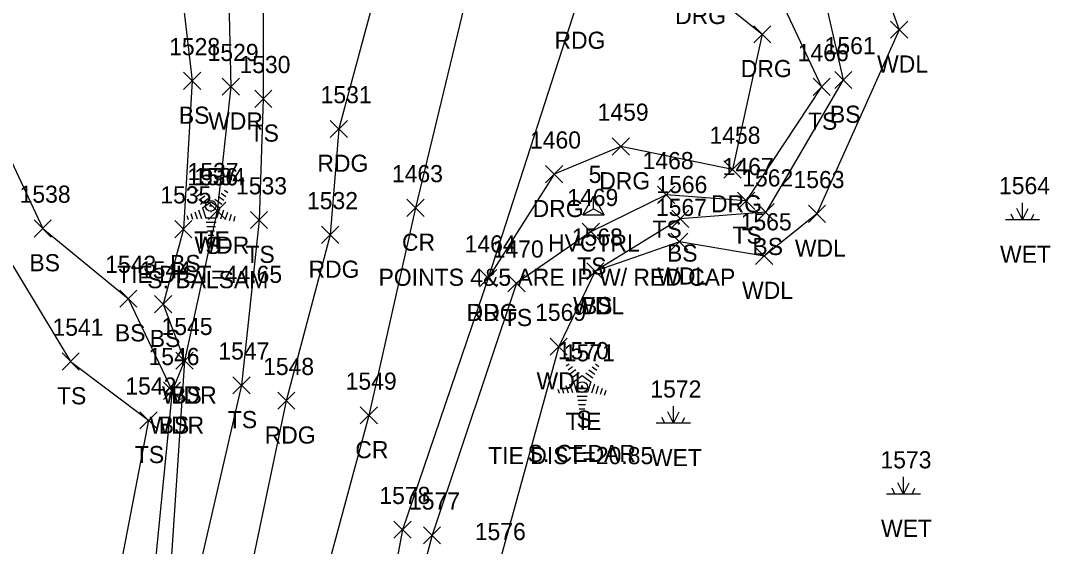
# Model space of a CAD drawing. Extents: x 1678553 to 1680768, y 787260 to 792325.
# Drawn here: x 1678621 to 1678741.1, y 787363.9 to 787425.2 of the extents above; entities that cross this region are included whole.
import ezdxf

# ---------------------------------------------------------------- set-up
doc = ezdxf.new("R2010")
doc.units = 0
for name, color, linetype in [('C_A', 7, 'Continuous'), ('C_C', 7, 'Continuous'), ('C_I', 7, 'Continuous'), ('CBP', 7, 'Continuous'), ('CPSM', 7, 'Continuous'), ('L_A', 7, 'Continuous'), ('L_C', 7, 'Continuous'), ('L_I', 7, 'Continuous'), ('L_TIC', 7, 'Continuous'), ('LAWA', 7, 'Continuous'), ('LELB', 7, 'Continuous'), ('LTC', 7, 'Continuous'), ('LWET', 7, 'Continuous'), ('P_A', 7, 'Continuous'), ('P_I', 7, 'Continuous'), ('P_TIC', 7, 'Continuous'), ('PEU', 7, 'Continuous'), ('PRC', 7, 'Continuous'), ('R_A', 7, 'Continuous'), ('R_I', 7, 'Continuous'), ('R_TIC', 7, 'Continuous'), ('RDG', 7, 'Continuous')]:
    doc.layers.add(name, color=color, linetype=linetype)

msp = doc.modelspace()

# ---------------------------------------------------------------- linework, layer by layer
at = {"layer": 'CBP'}
for centre, radius in [((1678643.19, 787403.64), 0.625), ((1678643.19, 787403.64), 0.0833), ((1678686.51, 787382.49), 0.625), ((1678686.51, 787382.49), 0.0833)]:
    msp.add_circle(centre, radius, dxfattribs=at)
at = {"layer": 'CPSM'}
for p, q in [((1678686.59, 787402.58), (1678687.84, 787404.75)), ((1678689.09, 787402.58), (1678687.84, 787404.75)), ((1678687.84, 787403.3), (1678687.84, 787404.75)), ((1678686.59, 787402.58), (1678687.84, 787403.3)), ((1678687.84, 787403.3), (1678687.84, 787403.3)), ((1678687.84, 787403.3), (1678689.09, 787402.58)), ((1678686.59, 787402.58), (1678689.09, 787402.58))]:
    msp.add_line(p, q, dxfattribs=at)
at = {"layer": 'L_TIC'}
for points in [[(1678722.5, 787423.18), (1678724.5, 787425.18)], [(1678724.5, 787423.18), (1678722.5, 787425.18)], [(1678640.03, 787417.21), (1678642.03, 787419.21)], [(1678642.03, 787417.21), (1678640.03, 787419.21)], [(1678644.53, 787416.53), (1678646.53, 787418.53)], [(1678646.53, 787416.53), (1678644.53, 787418.53)], [(1678713.45, 787416.51), (1678715.45, 787418.51)], [(1678715.45, 787416.51), (1678713.45, 787418.51)], [(1678715.98, 787417.32), (1678717.98, 787419.32)], [(1678717.98, 787417.32), (1678715.98, 787419.32)], [(1678648.32, 787415.12), (1678650.32, 787417.12)], [(1678650.32, 787415.12), (1678648.32, 787417.12)], [(1678695.31, 787403.91), (1678697.31, 787405.91)], [(1678697.31, 787403.91), (1678695.31, 787405.91)], [(1678704.65, 787403.22), (1678706.65, 787405.22)], [(1678706.65, 787403.22), (1678704.65, 787405.22)], [(1678642.94, 787402.04), (1678644.94, 787404.04)], [(1678644.94, 787402.04), (1678642.94, 787404.04)], [(1678647.83, 787400.97), (1678649.83, 787402.97)], [(1678649.83, 787400.97), (1678647.83, 787402.97)], [(1678696.96, 787401.12), (1678698.96, 787403.12)], [(1678698.96, 787401.12), (1678696.96, 787403.12)], [(1678706.93, 787401.89), (1678708.93, 787403.89)], [(1678708.93, 787401.89), (1678706.93, 787403.89)], [(1678712.91, 787401.7), (1678714.91, 787403.7)], [(1678714.91, 787401.7), (1678712.91, 787403.7)], [(1678622.59, 787399.99), (1678624.59, 787401.99)], [(1678624.59, 787399.99), (1678622.59, 787401.99)], [(1678639, 787399.91), (1678641, 787401.91)], [(1678641, 787399.91), (1678639, 787401.91)], [(1678686.53, 787399.61), (1678688.53, 787401.61)], [(1678688.53, 787399.61), (1678686.53, 787401.61)], [(1678696.86, 787398.45), (1678698.86, 787400.45)], [(1678698.86, 787398.45), (1678696.86, 787400.45)], [(1678706.75, 787396.77), (1678708.75, 787398.77)], [(1678708.75, 787396.77), (1678706.75, 787398.77)], [(1678687.05, 787394.99), (1678689.05, 787396.99)], [(1678689.05, 787394.99), (1678687.05, 787396.99)], [(1678687.05, 787394.99), (1678689.05, 787396.99)], [(1678689.05, 787394.99), (1678687.05, 787396.99)], [(1678677.86, 787393.6), (1678679.86, 787395.6)], [(1678679.86, 787393.6), (1678677.86, 787395.6)], [(1678632.57, 787391.81), (1678634.57, 787393.81)], [(1678634.57, 787391.81), (1678632.57, 787393.81)], [(1678636.64, 787391.16), (1678638.64, 787393.16)], [(1678638.64, 787391.16), (1678636.64, 787393.16)], [(1678682.78, 787386.21), (1678684.78, 787388.21)], [(1678684.78, 787386.21), (1678682.78, 787388.21)], [(1678625.85, 787384.47), (1678627.85, 787386.47)], [(1678627.85, 787384.47), (1678625.85, 787386.47)], [(1678639.14, 787384.56), (1678641.14, 787386.56)], [(1678641.14, 787384.56), (1678639.14, 787386.56)], [(1678639.14, 787384.56), (1678641.14, 787386.56)], [(1678641.14, 787384.56), (1678639.14, 787386.56)], [(1678645.78, 787381.69), (1678647.78, 787383.69)], [(1678647.78, 787381.69), (1678645.78, 787383.69)], [(1678637.68, 787381.05), (1678639.68, 787383.05)], [(1678639.68, 787381.05), (1678637.68, 787383.05)], [(1678637.68, 787381.05), (1678639.68, 787383.05)], [(1678639.68, 787381.05), (1678637.68, 787383.05)], [(1678634.93, 787377.61), (1678636.93, 787379.61)], [(1678636.93, 787377.61), (1678634.93, 787379.61)], [(1678668.01, 787364.19), (1678670.01, 787366.19)], [(1678670.01, 787364.19), (1678668.01, 787366.19)]]:
    msp.add_lwpolyline(points, dxfattribs=at)
at = {"layer": 'LAWA'}
for points in [[(1678709.78, 787516.49), (1678712.28, 787497.22), (1678701.79, 787461.31), (1678703.15, 787457.42), (1678705.06, 787457.53), (1678706.33, 787458.18), (1678713.92, 787445.73), (1678717.92, 787439.61), (1678723.5, 787424.18), (1678713.91, 787402.7), (1678707.75, 787397.77), (1678697.86, 787399.45), (1678688.05, 787395.99), (1678683.78, 787387.21), (1678676.74, 787361.63), (1678672.53, 787349.76), (1678668.76, 787338.44), (1678662.12, 787319.95), (1678654.2, 787273.36)], [(1678664.87, 787478.76), (1678656.17, 787475.05), (1678649.55, 787452.64), (1678645.06, 787437.85), (1678645.53, 787417.53), (1678643.94, 787403.04), (1678640.14, 787385.56), (1678638.68, 787382.05), (1678636.34, 787358.01), (1678630, 787335.83), (1678617.26, 787305.35), (1678619.26, 787283.6)]]:
    msp.add_lwpolyline(points, dxfattribs=at)
at = {"layer": 'LELB'}
for points in [[(1678703.25, 787521.16), (1678708.08, 787504.89), (1678710.05, 787496.73), (1678699.74, 787468.92), (1678698.82, 787457.49), (1678706.75, 787433.93), (1678714.45, 787417.51), (1678705.65, 787404.22), (1678696.31, 787404.91), (1678687.53, 787400.61), (1678678.86, 787394.6), (1678669.01, 787365.19), (1678664.74, 787349.08), (1678657.46, 787321.28), (1678652.34, 787297.83), (1678647.47, 787276.32)], [(1678680.77, 787518.06), (1678676.3, 787498.71), (1678671.38, 787486.28), (1678667.84, 787478.11), (1678658.92, 787472.2), (1678652.16, 787452.17), (1678649.27, 787436.42), (1678649.32, 787416.12), (1678648.83, 787401.97), (1678646.78, 787382.69), (1678641.04, 787357.73), (1678634.18, 787333.53), (1678626.23, 787302.07), (1678622.91, 787282.59)], [(1678670.34, 787510.61), (1678668.53, 787502.63), (1678666.36, 787491.77), (1678660.38, 787481.94), (1678643.3, 787471.26), (1678637.93, 787460.78), (1678638.18, 787442.6), (1678641.03, 787418.21), (1678640, 787400.91), (1678637.64, 787392.16), (1678640.14, 787385.56), (1678638.3, 787358.26), (1678630, 787335.83)], [(1678714.02, 787439.74), (1678712.73, 787436.98), (1678716.98, 787418.32), (1678707.93, 787402.89), (1678697.96, 787402.12), (1678688.05, 787395.99)], [(1678615.65, 787417.95), (1678623.59, 787400.99), (1678633.57, 787392.81), (1678638.68, 787382.05)], [(1678606.34, 787416.23), (1678617.44, 787401.01), (1678626.85, 787385.47), (1678635.93, 787378.61), (1678632.1, 787358.6), (1678630, 787335.83)]]:
    msp.add_lwpolyline(points, dxfattribs=at)
at = {"layer": 'LTC'}
for p, q in [((1678641.38, 787405.23), (1678641.74, 787405.49)), ((1678644.78, 787405.47), (1678645.2, 787405.17)), ((1678641.59, 787404.76), (1678642.12, 787405.15)), ((1678641.8, 787404.3), (1678642.51, 787404.81)), ((1678642.01, 787403.83), (1678642.89, 787404.47)), ((1678642.24, 787403.38), (1678643.25, 787404.11)), ((1678643.25, 787404.11), (1678644.25, 787403.39)), ((1678643.67, 787404.42), (1678644.48, 787403.84)), ((1678644.04, 787404.77), (1678644.72, 787404.28)), ((1678644.41, 787405.12), (1678644.96, 787404.72)), ((1678641.33, 787402.94), (1678641.6, 787402.11)), ((1678641.78, 787403.16), (1678642.11, 787402.14)), ((1678642.24, 787403.38), (1678642.62, 787402.18)), ((1678644.25, 787403.39), (1678643.85, 787402.18)), ((1678644.68, 787403.12), (1678644.35, 787402.08)), ((1678645.13, 787402.87), (1678644.84, 787401.98)), ((1678640.42, 787402.51), (1678640.57, 787402.04)), ((1678640.87, 787402.73), (1678641.08, 787402.07)), ((1678643.85, 787402.18), (1678642.62, 787402.18)), ((1678643.82, 787401.68), (1678642.67, 787401.68)), ((1678645.57, 787402.62), (1678645.34, 787401.89)), ((1678646.02, 787402.37), (1678645.83, 787401.79)), ((1678643.73, 787401.18), (1678642.74, 787401.18)), ((1678643.65, 787400.68), (1678642.82, 787400.68)), ((1678643.57, 787400.18), (1678642.89, 787400.18)), ((1678684.66, 787384.95), (1678685.01, 787385.2)), ((1678684.87, 787384.48), (1678685.4, 787384.87)), ((1678688.06, 787385.19), (1678688.48, 787384.88)), ((1678685.08, 787384.02), (1678685.78, 787384.53)), ((1678685.29, 787383.55), (1678686.17, 787384.19)), ((1678685.51, 787383.09), (1678686.52, 787383.83)), ((1678686.52, 787383.83), (1678687.52, 787383.1)), ((1678686.94, 787384.14), (1678687.75, 787383.55)), ((1678687.31, 787384.49), (1678687.99, 787384)), ((1678687.69, 787384.84), (1678688.24, 787384.44)), ((1678684.6, 787382.66), (1678684.87, 787381.82)), ((1678685.06, 787382.88), (1678685.39, 787381.86)), ((1678685.51, 787383.09), (1678685.9, 787381.9)), ((1678687.52, 787383.1), (1678687.13, 787381.9)), ((1678687.96, 787382.83), (1678687.62, 787381.79)), ((1678688.4, 787382.58), (1678688.12, 787381.7)), ((1678683.69, 787382.23), (1678683.84, 787381.76)), ((1678684.15, 787382.44), (1678684.36, 787381.79)), ((1678687.13, 787381.9), (1678685.9, 787381.9)), ((1678687.09, 787381.4), (1678685.95, 787381.4)), ((1678688.85, 787382.33), (1678688.61, 787381.6)), ((1678689.29, 787382.08), (1678689.1, 787381.51)), ((1678687.01, 787380.9), (1678686.02, 787380.9)), ((1678686.92, 787380.4), (1678686.09, 787380.4)), ((1678686.84, 787379.9), (1678686.16, 787379.9))]:
    msp.add_line(p, q, dxfattribs=at)
at = {"layer": 'LWET'}
for p, q in [((1678737.88, 787401.99), (1678737.21, 787403.32)), ((1678737.88, 787401.99), (1678737.88, 787403.99)), ((1678737.88, 787401.99), (1678738.54, 787403.32)), ((1678739.88, 787401.99), (1678735.88, 787401.99)), ((1678736.88, 787401.99), (1678736.54, 787402.66)), ((1678738.88, 787401.99), (1678739.21, 787402.66)), ((1678697.16, 787378.26), (1678697.16, 787380.26)), ((1678696.16, 787378.26), (1678695.83, 787378.92)), ((1678697.16, 787378.26), (1678696.5, 787379.59)), ((1678697.16, 787378.26), (1678697.83, 787379.59)), ((1678698.16, 787378.26), (1678698.5, 787378.92)), ((1678699.16, 787378.26), (1678695.16, 787378.26)), ((1678724, 787370), (1678724, 787372)), ((1678723, 787370), (1678722.67, 787370.67)), ((1678724, 787370), (1678723.33, 787371.33)), ((1678724, 787370), (1678724.67, 787371.33)), ((1678725, 787370), (1678725.33, 787370.67)), ((1678726, 787370), (1678722, 787370))]:
    msp.add_line(p, q, dxfattribs=at)
at = {"layer": 'P_TIC'}
for points in [[(1678657.14, 787411.6), (1678659.14, 787413.6)], [(1678659.14, 787411.6), (1678657.14, 787413.6)], [(1678666.07, 787402.39), (1678668.07, 787404.39)], [(1678668.07, 787402.39), (1678666.07, 787404.39)], [(1678656.12, 787399.24), (1678658.12, 787401.24)], [(1678658.12, 787399.24), (1678656.12, 787401.24)], [(1678674.55, 787394.19), (1678676.55, 787396.19)], [(1678676.55, 787394.19), (1678674.55, 787396.19)], [(1678651, 787379.89), (1678653, 787381.89)], [(1678653, 787379.89), (1678651, 787381.89)], [(1678660.63, 787378.18), (1678662.63, 787380.18)], [(1678662.63, 787378.18), (1678660.63, 787380.18)], [(1678664.56, 787364.84), (1678666.56, 787366.84)], [(1678666.56, 787364.84), (1678664.56, 787366.84)]]:
    msp.add_lwpolyline(points, dxfattribs=at)
at = {"layer": 'PEU'}
for points in [[(1678701.08, 787523.46), (1678691.86, 787521.67), (1678683.93, 787520.5), (1678679.42, 787498.09), (1678675.86, 787484.77), (1678672.35, 787466.03), (1678666.65, 787446.98), (1678662.98, 787430.65), (1678658.14, 787412.6), (1678657.12, 787400.24), (1678652, 787380.89), (1678646.8, 787355.99), (1678640.87, 787332.43), (1678631.51, 787300.96), (1678626.74, 787281.59)], [(1678701.08, 787523.46), (1678699.33, 787512.57), (1678697.82, 787495.04), (1678694.12, 787469.83), (1678689.97, 787450.94), (1678685.8, 787426.95), (1678675.55, 787395.19), (1678665.56, 787365.84), (1678662.4, 787349.05), (1678655.84, 787321.61), (1678650.23, 787298.04), (1678645.33, 787276.77)]]:
    msp.add_lwpolyline(points, dxfattribs=at)
at = {"layer": 'PRC'}
msp.add_lwpolyline([(1678691.86, 787521.67), (1678687.47, 787496.54), (1678683.41, 787472.73), (1678673.58, 787430.34), (1678667.07, 787403.39), (1678661.63, 787379.18), (1678654.8, 787353.83), (1678646.93, 787323.81), (1678641.79, 787300.31), (1678636.19, 787278.72)], dxfattribs=at)
at = {"layer": 'R_TIC'}
for points in [[(1678706.53, 787422.65), (1678708.53, 787424.65)], [(1678708.53, 787422.65), (1678706.53, 787424.65)], [(1678690.02, 787409.56), (1678692.02, 787411.56)], [(1678692.02, 787409.56), (1678690.02, 787411.56)], [(1678682.25, 787406.32), (1678684.25, 787408.32)], [(1678684.25, 787406.32), (1678682.25, 787408.32)], [(1678703.06, 787406.87), (1678705.06, 787408.87)], [(1678705.06, 787406.87), (1678703.06, 787408.87)], [(1678674.55, 787394.19), (1678676.55, 787396.19)], [(1678676.55, 787394.19), (1678674.55, 787396.19)]]:
    msp.add_lwpolyline(points, dxfattribs=at)
at = {"layer": 'RDG'}
msp.add_lwpolyline([(1678689.97, 787450.94), (1678694.13, 787437.37), (1678699.87, 787429.84), (1678707.53, 787423.65), (1678704.06, 787407.87), (1678691.02, 787410.56), (1678683.25, 787407.32), (1678675.55, 787395.19)], dxfattribs=at)

# ---------------------------------------------------------------- texts
at = {"layer": 'C_A'}
for s, p in [('TIE', (1678641.26, 787398.64)), ('HVCTRL', (1678682.54, 787398.3)), ('TIE', (1678684.59, 787377.49))]:
    msp.add_text(s, height=2, dxfattribs=at).set_placement(p)
at = {"layer": 'C_C'}
for s, p in [('TIE DIST=44.65', (1678632.27, 787394.64)), ('POINTS 4&5 ARE IP W/ RED CAP', (1678662.77, 787394.3)), ('TIE DIST=20.85', (1678675.56, 787373.49))]:
    msp.add_text(s, height=2, dxfattribs=at).set_placement(p)
at = {"layer": 'C_I'}
for s, p in [('1537', (1678640.49, 787406.64)), ('5', (1678687.28, 787406.3)), ('1571', (1678684.38, 787385.49))]:
    msp.add_text(s, height=2, dxfattribs=at).set_placement(p)
at = {"layer": 'L_A'}
for s, p in [('WDL', (1678720.92, 787419.18)), ('BS', (1678639.47, 787413.21)), ('BS', (1678715.42, 787413.32)), ('WDR', (1678642.89, 787412.53)), ('TS', (1678712.86, 787412.51)), ('TS', (1678647.73, 787411.12)), ('TS', (1678694.71, 787399.91)), ('TS', (1678704.06, 787399.22)), ('WDR', (1678641.3, 787398.04)), ('S', (1678642.57, 787398.02)), ('BS', (1678706.38, 787397.89)), ('WDL', (1678711.33, 787397.7)), ('TS', (1678647.24, 787396.97)), ('BS', (1678696.41, 787397.12)), ('WET', (1678735.26, 787396.99)), ('BS', (1678622.04, 787395.99)), ('BS', (1678638.45, 787395.91)), ('TS', (1678685.94, 787395.61)), ('WDL', (1678695.28, 787394.45)), ('WDL', (1678705.17, 787392.77)), ('WDL', (1678685.47, 787390.99)), ('BS', (1678686.49, 787390.99)), ('TS', (1678677.27, 787389.6)), ('BS', (1678632.01, 787387.81)), ('BS', (1678636.08, 787387.16)), ('WDL', (1678681.2, 787382.21)), ('TS', (1678625.26, 787380.47)), ('WDR', (1678637.5, 787380.56)), ('BS', (1678638.58, 787380.56)), ('WDR', (1678636.04, 787377.05)), ('BS', (1678637.12, 787377.05)), ('TS', (1678645.19, 787377.69)), ('S', (1678685.85, 787377.74)), ('TS', (1678634.34, 787373.61)), ('WET', (1678694.54, 787373.26)), ('WET', (1678721.38, 787365))]:
    msp.add_text(s, height=2, dxfattribs=at).set_placement(p)
at = {"layer": 'L_C'}
for s, p in [('S. BALSAM', (1678635.79, 787394.02)), ('S. CEDAR', (1678680.16, 787373.74))]:
    msp.add_text(s, height=2, dxfattribs=at).set_placement(p)
at = {"layer": 'L_I'}
for s, p in [('1561', (1678714.8, 787421.32)), ('1528', (1678638.34, 787421.21)), ('1529', (1678642.83, 787420.53)), ('1466', (1678711.66, 787420.51)), ('1530', (1678646.54, 787419.12)), ('1468', (1678693.57, 787407.91)), ('1467', (1678702.91, 787407.22)), ('1536', (1678640.44, 787406.02)), ('1534', (1678641.24, 787406.04)), ('1562', (1678705.19, 787405.89)), ('1563', (1678711.17, 787405.7)), ('1533', (1678646.14, 787404.97)), ('1566', (1678695.17, 787405.12)), ('1564', (1678735.14, 787404.99)), ('1538', (1678620.9, 787403.99)), ('1535', (1678637.31, 787403.91)), ('1469', (1678684.78, 787403.61)), ('1567', (1678695.12, 787402.45)), ('1565', (1678705.01, 787400.77)), ('1568', (1678685.31, 787398.99)), ('1568', (1678685.31, 787398.99)), ('1470', (1678676.08, 787397.6)), ('1543', (1678630.88, 787395.81)), ('1544', (1678634.94, 787395.16)), ('1569', (1678681.03, 787390.21)), ('1541', (1678624.73, 787388.47)), ('1545', (1678637.45, 787388.56)), ('1545', (1678637.45, 787388.56)), ('1547', (1678644.08, 787385.69)), ('1570', (1678683.68, 787385.74)), ('1546', (1678635.93, 787385.05)), ('1546', (1678635.93, 787385.05)), ('1542', (1678633.23, 787381.61)), ('1572', (1678694.47, 787381.26)), ('1573', (1678721.31, 787373)), ('1577', (1678666.32, 787368.19)), ('1576', (1678673.99, 787364.63))]:
    msp.add_text(s, height=2, dxfattribs=at).set_placement(p)
at = {"layer": 'LTC'}
for p in [(1678643.13, 787403.13), (1678686.41, 787382.84)]:
    msp.add_text('.', height=1.04, rotation=270, dxfattribs=at).set_placement(p)
at = {"layer": 'P_A'}
for s, p in [('RDG', (1678683.29, 787421.95)), ('RDG', (1678655.63, 787407.6)), ('CR', (1678665.5, 787398.39)), ('RDG', (1678654.6, 787395.24)), ('RDG', (1678673.04, 787390.19)), ('RDG', (1678649.48, 787375.89)), ('CR', (1678660.06, 787374.18))]:
    msp.add_text(s, height=2, dxfattribs=at).set_placement(p)
at = {"layer": 'P_I'}
for s, p in [('1531', (1678656.01, 787415.6)), ('1463', (1678664.33, 787406.39)), ('1532', (1678654.42, 787403.24)), ('1464', (1678672.81, 787398.19)), ('1548', (1678649.3, 787383.89)), ('1549', (1678658.93, 787382.18)), ('1578', (1678662.86, 787368.84))]:
    msp.add_text(s, height=2, dxfattribs=at).set_placement(p)
at = {"layer": 'R_A'}
for p in [(1678697.36, 787424.84), (1678705.02, 787418.65), (1678688.51, 787405.56), (1678680.74, 787402.32), (1678701.55, 787402.87), (1678673.04, 787390.19)]:
    msp.add_text('DRG', height=2, dxfattribs=at).set_placement(p)
at = {"layer": 'R_I'}
for s, p in [('1459', (1678688.32, 787413.56)), ('1458', (1678701.37, 787410.87)), ('1460', (1678680.43, 787410.32)), ('1464', (1678672.81, 787398.19))]:
    msp.add_text(s, height=2, dxfattribs=at).set_placement(p)

doc.saveas('drawing.dxf')
